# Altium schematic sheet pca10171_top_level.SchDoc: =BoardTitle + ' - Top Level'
size A3; Organization: Nordic Semiconductor; DocumentNumber: 1; SheetNumber: 1; SheetTotal: 10; CompanyName: Nordic Semiconductor; DocumentSize: A3
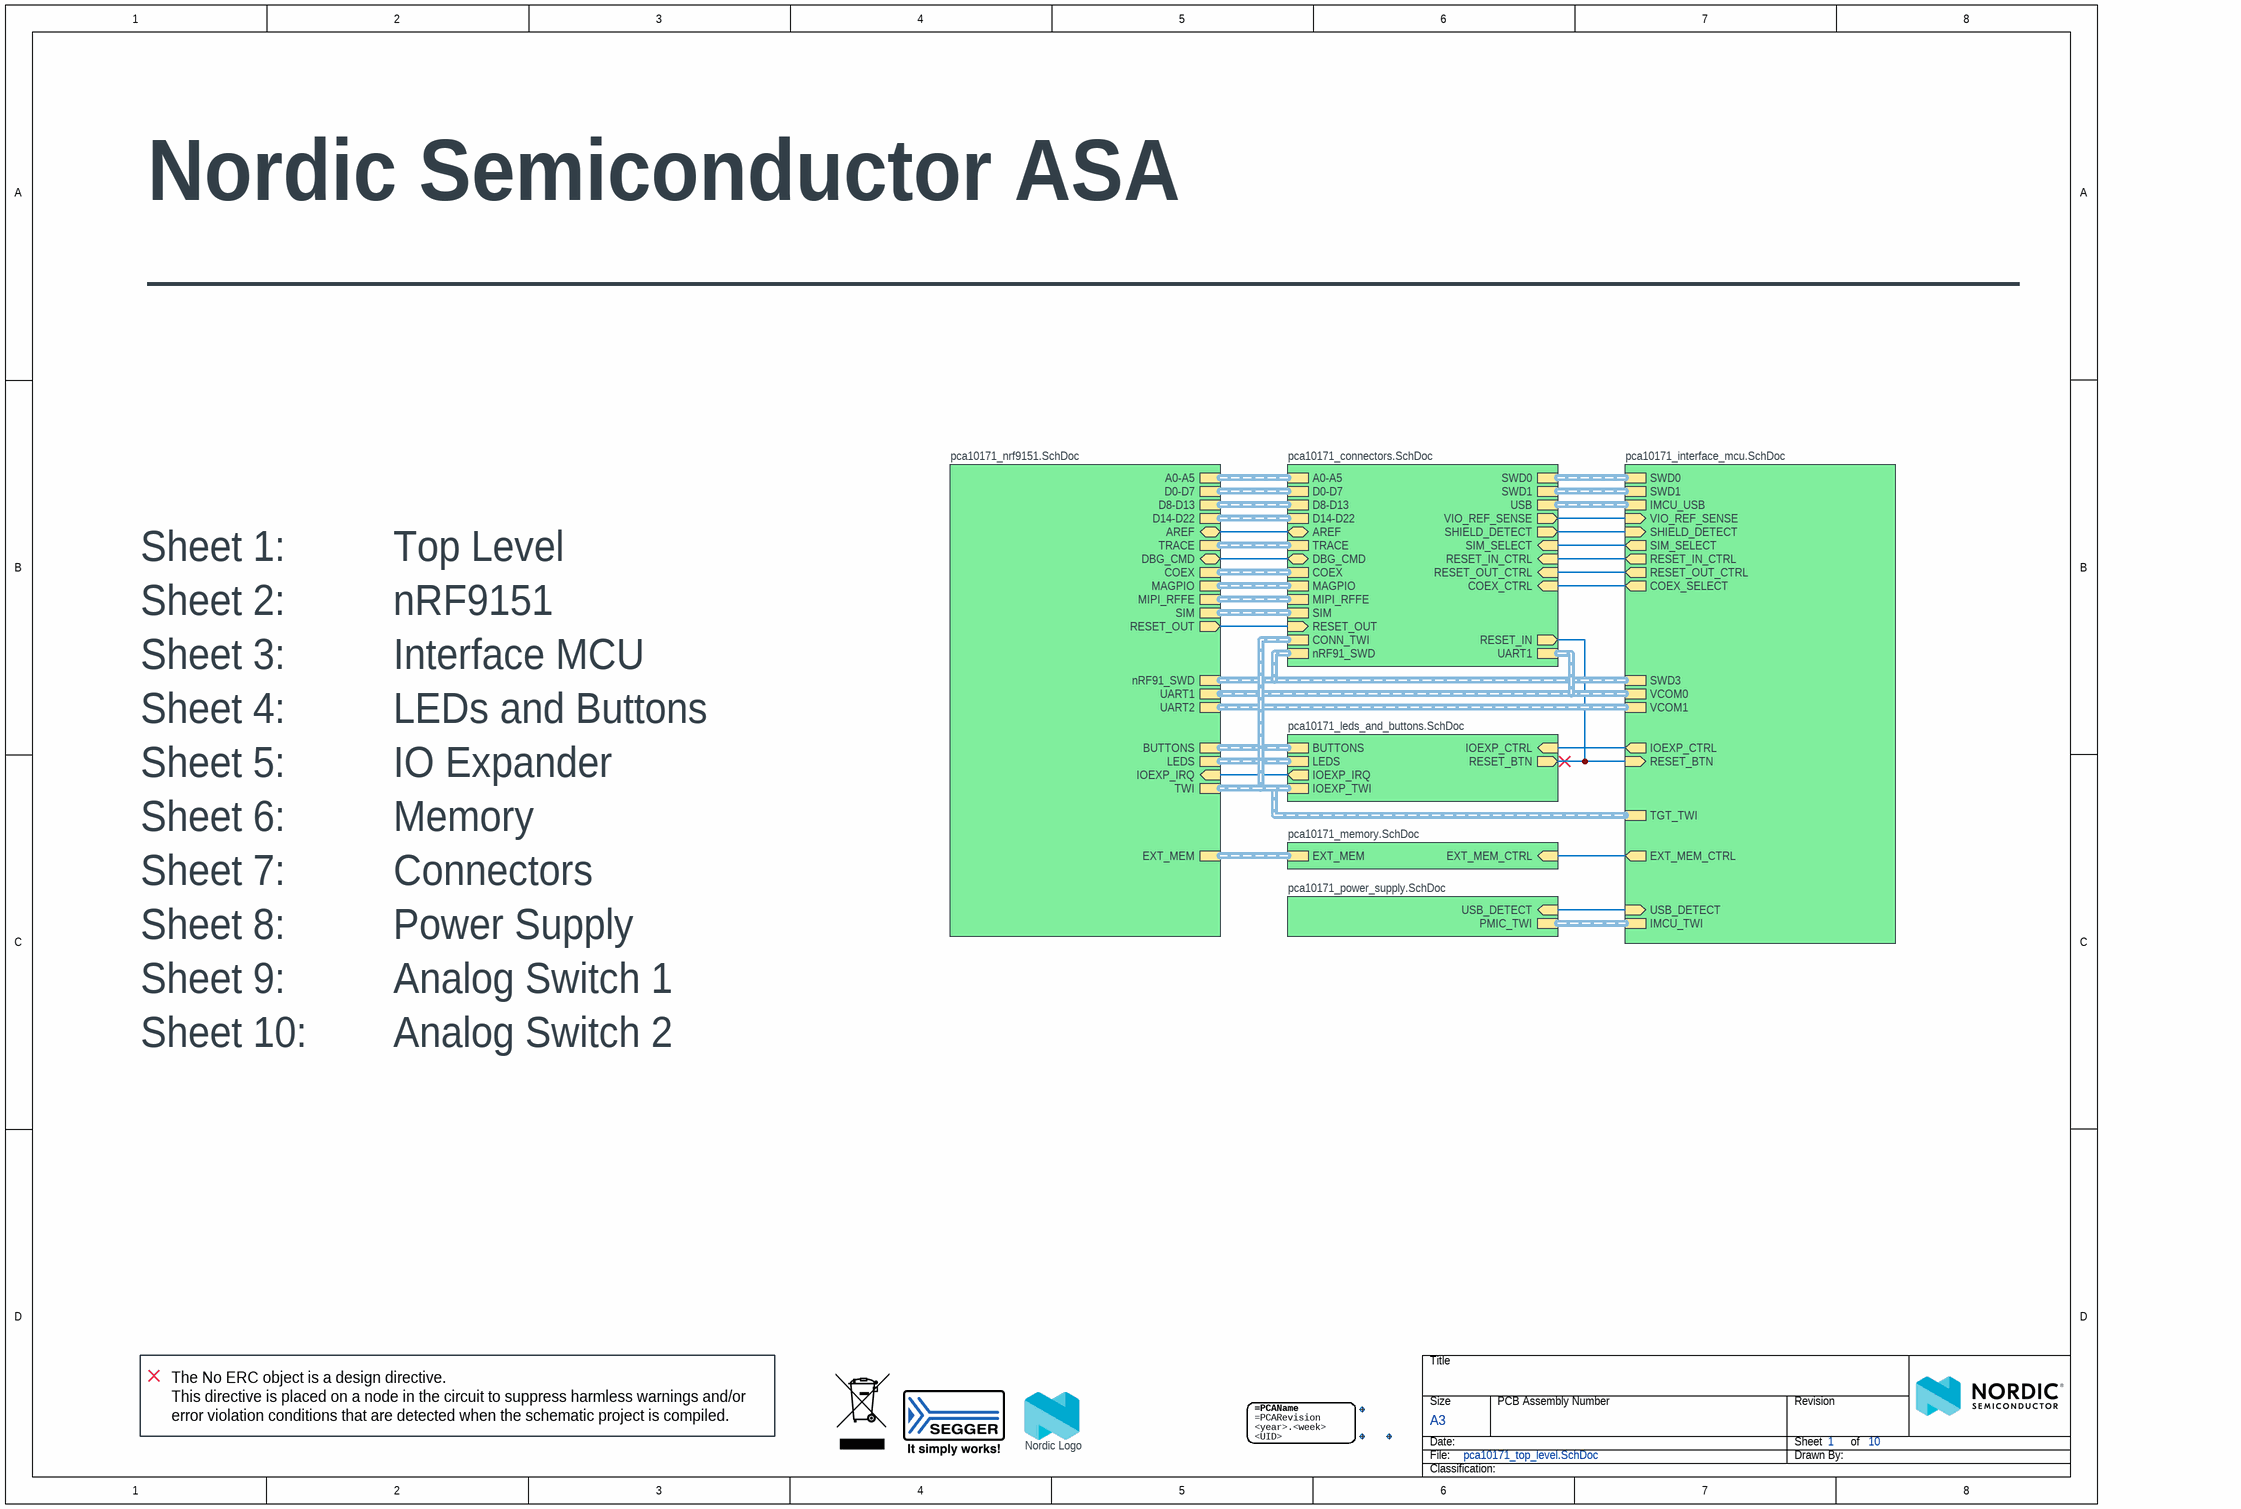
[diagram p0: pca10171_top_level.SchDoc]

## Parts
Fid1  Fiducial mark  [Fiducial]  (value not drawn)  (no BOM)
Fid2  Fiducial mark  [Fiducial]  (value not drawn)  (no BOM)
Fid3  Fiducial mark  [Fiducial]  (value not drawn)  (no BOM)
LABEL1  15x40mm  [LabelSilk_15x40]  (value not drawn)
LOGO1  WEE Symbol  [WEE_3x4.5mm]  (value not drawn)  (no BOM)
LOGO2  Segger Logo S  [SEGGER_LOGO_S]  (value not drawn)  (no BOM)
LOGO3  Nordic Logo  [NORDIC_LOGO_LYING]  (no BOM)

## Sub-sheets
? = pca10171_nrf9151.SchDoc: nRF91_SWD (harness SWD), DBG_CMD (bidir), UART1 (harness UART), COEX (harness COEX), UART2 (harness UART), SIM (harness SIM), TWI (harness TWI), A0-A5 (harness 6CH), AREF (bidir), TRACE (harness TRACE), BUTTONS (harness 4CH), LEDS (harness 4CH), IOEXP_IRQ (in), EXT_MEM (harness SPI), MIPI_RFFE (harness MIPI_RFFE), MAGPIO (harness MAGPIO), RESET_OUT (out), D8-D13 (harness 6CH), D14-D22 (harness 9CH), D0-D7 (harness 8CH)
? = pca10171_interface_mcu.SchDoc: VCOM1 (harness UART), VCOM0 (harness UART), USB_DETECT (in), RESET_BTN (in), SWD3 (harness SWD), SWD1 (harness SWD), IMCU_USB (harness USB), SWD0 (harness SWD), COEX_SELECT (out), IOEXP_CTRL (out), SIM_SELECT (out), TGT_TWI (harness TWI), VIO_REF_SENSE (in), IMCU_TWI (harness TWI), RESET_IN_CTRL (out), EXT_MEM_CTRL (out), SHIELD_DETECT (in), RESET_OUT_CTRL (out)
? = pca10171_leds_and_buttons.SchDoc: BUTTONS (harness 4CH), LEDS (harness 4CH), IOEXP_CTRL (in), IOEXP_IRQ (out), RESET_BTN (out), IOEXP_TWI (harness TWI)
? = pca10171_memory.SchDoc: EXT_MEM_CTRL (in), EXT_MEM (harness SPI)
? = pca10171_connectors.SchDoc: COEX (harness COEX), nRF91_SWD (harness SWD), DBG_CMD (bidir), MIPI_RFFE (harness MIPI_RFFE), A0-A5 (harness 6CH), TRACE (harness TRACE), USB (harness USB), SIM (harness SIM), AREF (bidir), MAGPIO (harness MAGPIO), SWD0 (harness SWD), SWD1 (harness SWD), SHIELD_DETECT (out), UART1 (harness UART), SIM_SELECT (in), VIO_REF_SENSE (out), CONN_TWI (harness TWI), RESET_IN_CTRL (in), RESET_OUT (in), RESET_OUT_CTRL (in), RESET_IN (out), D8-D13 (harness 6CH), D14-D22 (harness 9CH), D0-D7 (harness 8CH), COEX_CTRL (in)
? = pca10171_power_supply.SchDoc: USB_DETECT (in), PMIC_TWI (harness TWI)

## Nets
(unnamed): sheet /DBG_CMD, sheet /DBG_CMD
(unnamed): sheet /AREF, sheet /AREF  [a separate net that carries the same name]
(unnamed): sheet /IOEXP_IRQ, sheet /IOEXP_IRQ  [a separate net that carries the same name]
(unnamed): sheet /RESET_OUT, sheet /RESET_OUT  [a separate net that carries the same name]
(unnamed): sheet /USB_DETECT, sheet /USB_DETECT  [a separate net that carries the same name]
(unnamed): sheet /RESET_BTN, sheet /RESET_BTN, sheet /RESET_IN  [a separate net that carries the same name]
(unnamed): sheet /COEX_SELECT, sheet /COEX_CTRL  [a separate net that carries the same name]
(unnamed): sheet /IOEXP_CTRL, sheet /IOEXP_CTRL  [a separate net that carries the same name]
(unnamed): sheet /SIM_SELECT, sheet /SIM_SELECT  [a separate net that carries the same name]
(unnamed): sheet /VIO_REF_SENSE, sheet /VIO_REF_SENSE  [a separate net that carries the same name]
(unnamed): sheet /RESET_IN_CTRL, sheet /RESET_IN_CTRL  [a separate net that carries the same name]
(unnamed): sheet /EXT_MEM_CTRL, sheet /EXT_MEM_CTRL  [a separate net that carries the same name]
(unnamed): sheet /SHIELD_DETECT, sheet /SHIELD_DETECT  [a separate net that carries the same name]
(unnamed): sheet /RESET_OUT_CTRL, sheet /RESET_OUT_CTRL  [a separate net that carries the same name]

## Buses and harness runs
harness sheet /CONN_TWI = sheet /IOEXP_TWI = sheet /TGT_TWI = sheet /TWI
harness sheet /IMCU_TWI = sheet /PMIC_TWI
harness sheet /IMCU_USB = sheet /USB
harness sheet /nRF91_SWD = sheet /SWD3
harness sheet /UART1 = sheet /VCOM0
harness sheet /UART2 = sheet /VCOM1

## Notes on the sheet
- Nordic Semiconductor ASA
- ________________________________________________________________
- Sheet 1:          Top Level
- Sheet 2:          nRF9151
- Sheet 3:          Interface MCU
- Sheet 4:          LEDs and Buttons
- Sheet 5:          IO Expander
- Sheet 6:          Memory
- Sheet 7:          Connectors
- Sheet 8:          Power Supply
- Sheet 9:          Analog Switch 1
- Sheet 10:        Analog Switch 2
- The No ERC object is a design directive.
  This directive is placed on a node in the circuit to suppress harmless warnings and/or error violation conditions that are detected when the schematic project is compiled.

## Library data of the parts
Fid1-Fid3 = Fid-Mark: Manufacturer: N.A.; Part number NEMS: 100500073; Value: N.A.; Assembly: Not mounted; Pad Count: 1; Component Status: Active; System: Connector
LABEL1 = Label_15x40: PCA version label, stick-on, 15x40mm; Manufacturer: Ellco Etikett; Manufacturer Part Number: 51945; Part number NEMS: 101200030; Component Status: Active; Pad Count: 0; Note: N.A.; Assembly: See section for "Marking/ Stick-on label specification
LOGO1 = WEEE Symbol 3x4.5mm: WEEE Directive symbol; Manufacturer: N.A.; Part number NEMS: 101100006; Component Status: Active; Pad Count: 0
LOGO2 = Segger Logo S: Segger logo, small size; Manufacturer: N.A.; Part number NEMS: 101100004; Component Status: Active; Pad Count: 0
LOGO3 = Nordic Logo lying: Manufacturer: N.A.; Part number NEMS: 101100001; Component Status: Active; Pad Count: 0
